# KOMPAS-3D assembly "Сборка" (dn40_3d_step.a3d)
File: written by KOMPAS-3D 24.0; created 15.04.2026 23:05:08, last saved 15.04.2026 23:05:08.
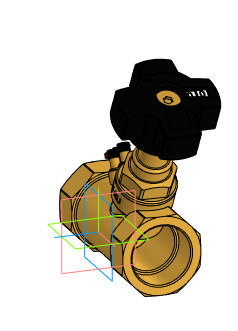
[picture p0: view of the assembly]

Document properties: Автор: tyuri; Полное имя файла: D:\Аутсорс\VB0000P-T Клапан балансировочный статический DN.ru\DN40\Исходные данные\dn40_3d_step.a3d

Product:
- Component [detail]: Деталь1  | qty 1  | Автор: tyuri; source file: Деталь1 - Деталь1.m3d
- Component [detail]: Деталь2  | qty 1  | Автор: tyuri; source file: Деталь2 - Деталь2.m3d
- Part/product: Сборка

Referenced files in D:\Аутсорс\VB0000P-T Клапан балансировочный статический DN.ru\DN40\Исходные данные\: Деталь1 - Деталь1.m3d, Деталь2 - Деталь2.m3d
